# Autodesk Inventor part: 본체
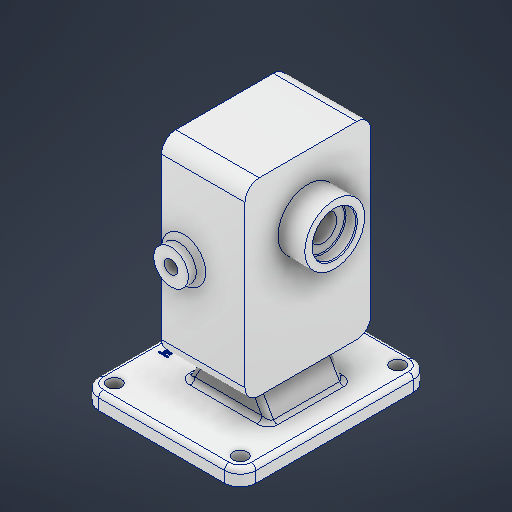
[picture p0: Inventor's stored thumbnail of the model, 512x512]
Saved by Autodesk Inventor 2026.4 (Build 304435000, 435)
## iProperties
Created: 2026-10
Part Number: 본체
Material: 알루미늄 6061
Document SubType Name: Modeling
Designer: user
Density: 2.7 g/cm^3
Appearance: 알루미늄 - 평지
Mass: 1474.42 g
Surface Area: 824.498 cm^2
Volume: 546.08 cm^3
Author: user
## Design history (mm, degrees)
sketch "스케치1"
  geometry: L1 (50, -60)-(-50, -60); L2 (-50, -60)-(-50, 60); L3 (-50, 60)-(50, 60); L4 (50, 60)-(50, -60); 1 further point
  constraints: 8 end point, 2 parallel, 1 horizontal, 1 perpendicular
  dimensions: "d0" = 100 distance of L2.end L3.end; "d1" = 120 distance of L3.end L1.start; "d2" = 60 distance from line of point (0, 0) L1; "d3" = 50 distance from line of point (0, 0) L4
extrude "돌출1" new body sketch "스케치1" distance "d4" = 10; taper "d5" = 0 deg
fillet "모깎기1" dims "d6" = 10
sketch "스케치2"
  geometry: C1 r 4.5 at (-40, 50); A1 r 10 centre (-40, 50) between (-40, 60) and (-50, 50) reference; 1 further point
  constraints: 1 centre point, 1 coincident
  dimensions: "d7" = 4.5 radius of C1
extrude "돌출2" cut sketch "스케치2" extent not by distance; stored distance "d8" = 0; taper "d9" = 0 deg
node "작업 평면1"
sketch "스케치3"
  geometry: L1 (10, 150)-(90, 150); L2 (90, 150)-(90, 30); L3 (90, 30)-(10, 30); L4 (10, 30)-(10, 150); L5 (0, 0)-(100, 0) reference; 3 further points
  constraints: 8 end point, 2 midpoint, 2 parallel, 1 horizontal, 1 perpendicular
  dimensions: "d11" = 120 distance of L3.end L1.start; "d12" = 80 distance of L1.start L1.end; "d13" = 90 distance from line of L5 point (10, 90); "d14" = 40 distance from line of point (50, 0) L4
extrude "돌출3" join sketch "스케치3" distance "d15" = 53; taper "d16" = 0 deg
sketch "스케치4"
  geometry: L1 (40, 10)-(-40, 10) reference; L2 (-20, 10)-(-3.032, 39.39); L3 (-3.032, 39.39)-(16.032, 39.39); L4 (33, 30)-(-20, 30) reference; L5 (16.032, 39.39)-(33, 10); L6 (35.5, 10)-(44.5, 10) reference; L7 (-20, 10)-(33, 10); L8 (50, 10)-(50, 0) reference; 1 further point
  constraints: 8 end point, 2 parallel, 2 point on line, 1 horizontal alignment
  dimensions: "d17" = 60 deg angle of L1 L5; "d18" = 60 deg angle of L1 L2; "d19" = 17 distance from line of L8 L5.end; "d20" = 29.38963 distance between parallel lines of L1 L3; "d21" = 53 distance of L5.end L2.start
extrude "돌출4" join sketch "스케치4" stored distance "d22" = 48; taper "d23" = 0 deg
sketch "스케치5"
  geometry: L1 (-50, 112)-(-50, 68); L2 (-74, 112)-(-74, 68); L3 (-26, 68)-(-26, 112); L4 (-90, 150)-(-90, 30) reference; L5 (-100, 10)-(0, 10) reference; A1 r 24 centre (-50, 112) between (-26, 112) and (-74, 112); A2 r 24 centre (-50, 68) between (-74, 68) and (-26, 68); 4 further points
  constraints: 8 end point, 4 point on circle, 4 tangent, 3 midpoint, 2 centre point, 1 horizontal alignment, 1 parallel, 1 vertical, 1 vertical alignment
  dimensions: "d24" = 24 radius of A2; "d25" = 44 distance of L1.start L1.end
extrude "돌출5" cut sketch "스케치5" distance "d26" = 29; taper "d27" = 0 deg
sketch "스케치6"
  geometry: C1 r 12.5 at (-50, 68); A1 r 24 centre (-50, 68) between (-74, 68) and (-26, 68) reference; 1 further point
  constraints: 1 centre point, 1 coincident
  dimensions: "d28" = 12.5 radius of C1
extrude "돌출6" cut sketch "스케치6" distance "d29" = 15; taper "d30" = 0 deg
sketch "스케치7"
  geometry: C1 r 12.5 at (-50, 112); A1 r 24 centre (-50, 112) between (-26, 112) and (-74, 112) reference; 1 further point
  constraints: 1 centre point, 1 coincident
  dimensions: "d31" = 12.5 radius of C1
extrude "돌출7" cut sketch "스케치7" distance "d32" = 15; taper "d33" = 0 deg
sketch "스케치9"
  geometry: C1 r 19 at (50, 112); A1 r 24 centre (50, 112) between (74, 112) and (26, 112) reference; 1 further point
  constraints: 1 centre point, 1 coincident
  dimensions: "d34" = 19 radius of C1
extrude "돌출8" join sketch "스케치9" distance "d35" = 17; taper "d36" = 0 deg
sketch "스케치10"
  geometry: C1 r 14 at (0, 0); A1 r 24 centre (0, 0) between (24, 0) and (-24, 0) reference; 1 further point
  constraints: 1 centre point, 1 coincident
  dimensions: "d37" = 14 radius of C1
extrude "돌출9" cut sketch "스케치10" distance "d38" = 7.3; taper "d39" = 0 deg
sketch "스케치11"
  geometry: C1 r 12.5 at (0, 0) reference; C2 r 8.5 at (0, 0); 1 further point
  constraints: 1 centre point, 1 coincident
  dimensions: "d40" = 8.5 radius of C2
extrude "돌출10" cut sketch "스케치11" extent not by distance; stored distance "d41" = 0; taper "d42" = 0 deg
sketch "스케치12"
  geometry: L1 (53, 120)-(53, 0) reference; L2 (-7, -30)-(73, -30) reference; C1 r 11 at (39, 60); 2 further points
  constraints: 1 centre point, 1 midpoint
  dimensions: "d43" = 11 radius of C1; "d44" = 14 distance of point (53, 60) C1.centre; "d45" = 90 distance from line of L2 C1.centre
extrude "돌출11" join sketch "스케치12" distance "d46" = 8; taper "d47" = 0 deg
fillet "모깎기2" dims "d48" = 3
fillet "모깎기3" dims "d49" = 9
fillet "모깎기4" dims "d50" = 3
chamfer "모따기1" distance "d51" = 1; stored, may be unused: second distance "d52" = 2, angle "d53" = 45 deg
fillet "모깎기5" dims "d54" = 0.5
chamfer "모따기2" distance "d55" = 0.7; stored, may be unused: second distance "d56" = 2, angle "d57" = 30 deg
sketch "스케치14"
  geometry: 1 further point
sketch "스케치15"
  geometry: C1 r 11 at (0, 0) reference; 2 further points
  constraints: 1 coincident
hole "구멍2" sketch "스케치15" diameter "d67" = 8; stored, may be unused: countersink angle "d73" = 82 deg, drill point angle "d75" = 0 deg; dims "d68" = 7.4, "d69" = 0.62479, "d70" = 7.985, "d71" = 3.023, "d72" = 2, "d74" = 30.9
sketch "스케치18"
  geometry: L1 (-50, 50)-(-50, -50) reference; 3 further points
  constraints: 1 horizontal alignment, 1 midpoint, 1 other
  dimensions: "d76" = 10 distance from line of L1 point (-40, 0)
feature "엠보싱1" sketch "스케치18" dims "d0" = 100, "d1" = 120, "d2" = 60, "d3" = 50, "d77" = 0.5, "d78" = 0
sketch "스케치19"
  geometry: C1 r 2.067 at (-81, 141) reference; C2 r 2.067 at (-81, 39) reference; 5 further points
  constraints: 2 coincident, 2 vertical alignment
  dimensions: "d79" = 29 distance of point (-81, 141) point (-81, 112); "d80" = 29 distance of C2.centre point (-81, 68)
hole "구멍3" sketch "스케치19" at (-81, 141), (-81, 112), (-81, 68), (-81, 39) diameter "d81" = 4.134; stored, may be unused: countersink angle "d85" = 90 deg, drill point angle "d87" = 118 deg; dims "d82" = 10, "d83" = 4, "d84" = 2, "d86" = 12
node "솔리드1"
mirror "미러1"
mirror "미러2"
mirror "미러3"
mirror "미러5"
mirror "미러6"
feature "A9D066F2-1C7D-4E18-AEED-F7BC21143FA4" dims "d67" = 8, "d68" = 7.4, "d69" = 0.62479, "d70" = 7.985, "d71" = 3.023, "d72" = 2, "d73" = 82 deg, "d74" = 30.9, "d75" = 0
other parameters: "d10" = -17
